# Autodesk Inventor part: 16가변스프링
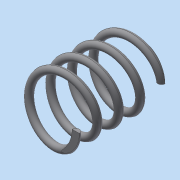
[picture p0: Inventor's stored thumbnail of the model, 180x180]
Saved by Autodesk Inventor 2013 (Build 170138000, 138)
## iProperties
Created: 2015-09
Part Number: 16가변스프링
Material: 일반
Document SubType Name: Modeling
Designer: dgall
Density: 1 g/cm^3
Author: dgall
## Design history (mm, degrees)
sketch "스케치1"
  geometry: L1 (8, 0)-(0, 0); L2 (0, 0)-(0, 42); L3 (0, 42)-(8, 42); C1 r 1 at (8, 0)
  constraints: 6 end point, 1 centre point, 1 coincident, 1 horizontal, 1 parallel, 1 perpendicular, 1 vertical alignment
  dimensions: "d0" = 42 distance of L1.end L2.end (derived); "d1" = 16 diameter of L1.start L2; "d2" = 2 diameter of C1
feature "코일1" pitch "d3" = 10; turns "d5" = 4; dims "d4" = 42 (= d0), "d6" = 0, angle "d7" = 90 deg, angle "d8" = 90 deg, "d9" = 0, "d10" = 0
feature "분할1"
node "작업 평면1"
feature "분할2"
node "솔리드1"
other parameters: "d11" = 24
